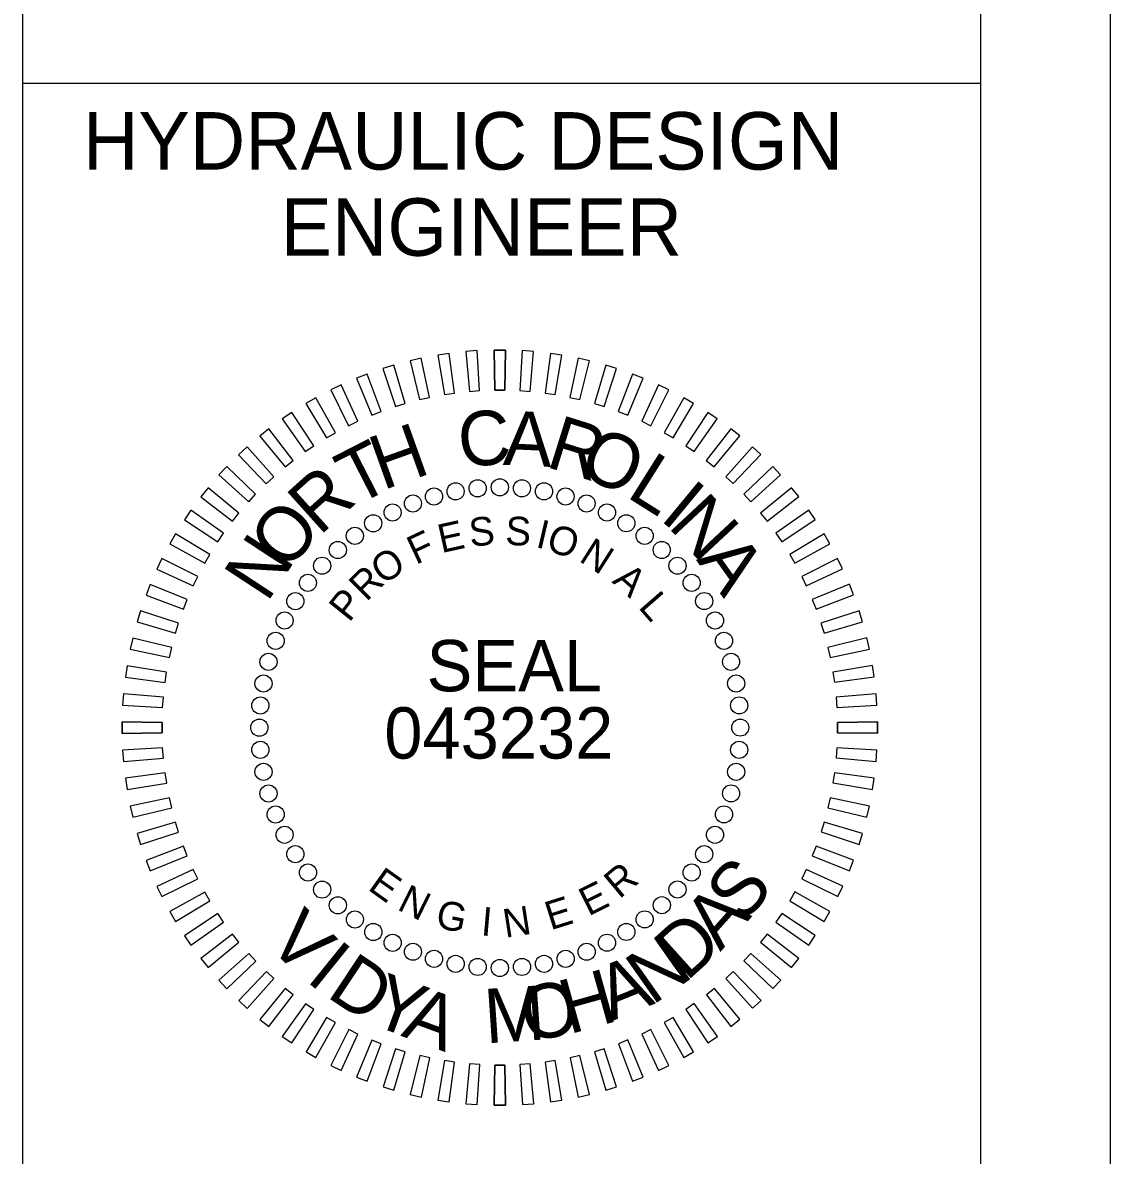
# Model space of a CAD drawing. Extents: x -0.56 to 3.44, y 0 to 1.83.
# Drawn here: x 2.6441 to 2.8333, y 1.3567 to 1.5538 of the extents above; entities that cross this region are included whole.
import ezdxf

# ---------------------------------------------------------------- set-up
doc = ezdxf.new("R2010")
doc.units = 0
for name, color, linetype in [('Default', 7, 'Continuous'), ('Scratch_Level_0', 7, 'Continuous'), ('Sheet PE Seal Cell', 7, 'Continuous'), ('Sheet Plan CELL', 7, 'Continuous'), ('Sheet_Plan_CELL', 7, 'Continuous')]:
    doc.layers.add(name, color=color, linetype=linetype)

msp = doc.modelspace()

# ---------------------------------------------------------------- linework, layer by layer
at = {"layer": 'Scratch_Level_0'}
msp.add_line((2.8333, 0), (2.8333, 1.8333), dxfattribs=at)
at = {"layer": 'Sheet PE Seal Cell'}
for p, q in [((2.71827, 1.49622), (2.7163, 1.49593)), ((2.7192, 1.48932), (2.71827, 1.49622)), ((2.72316, 1.4967), (2.72118, 1.49655)), ((2.72118, 1.49655), (2.7218, 1.48961)), ((2.72358, 1.48974), (2.72316, 1.4967)), ((2.72808, 1.49681), (2.72609, 1.49681)), ((2.72609, 1.49681), (2.7262, 1.48984)), ((2.72609, 1.49681), (2.72808, 1.49681)), ((2.7262, 1.48984), (2.72609, 1.49681)), ((2.72797, 1.48984), (2.72808, 1.49681)), ((2.72808, 1.49681), (2.72797, 1.48984)), ((2.731, 1.4967), (2.73059, 1.48974)), ((2.73298, 1.49655), (2.731, 1.4967)), ((2.73237, 1.48961), (2.73298, 1.49655)), ((2.73589, 1.49623), (2.73496, 1.48932)), ((2.73786, 1.49593), (2.73589, 1.49623)), ((2.70866, 1.49419), (2.70677, 1.49359)), ((2.71062, 1.4875), (2.70866, 1.49419)), ((2.71343, 1.49539), (2.71148, 1.49495)), ((2.71148, 1.49495), (2.71314, 1.48817)), ((2.71487, 1.48857), (2.71343, 1.49539)), ((2.7163, 1.49593), (2.71745, 1.48905)), ((2.73672, 1.48905), (2.73786, 1.49593)), ((2.74073, 1.49539), (2.73928, 1.48857)), ((2.74268, 1.49495), (2.74073, 1.49539)), ((2.74103, 1.48817), (2.74268, 1.49495)), ((2.74551, 1.49419), (2.74355, 1.48749)), ((2.7474, 1.4936), (2.74551, 1.49419)), ((2.70399, 1.49263), (2.70214, 1.4919)), ((2.70645, 1.4861), (2.70399, 1.49263)), ((2.70677, 1.49359), (2.70892, 1.48697)), ((2.74525, 1.48697), (2.7474, 1.4936)), ((2.75016, 1.49263), (2.74771, 1.48611)), ((2.75202, 1.49191), (2.75016, 1.49263)), ((2.69947, 1.49073), (2.69767, 1.48987)), ((2.70239, 1.48441), (2.69947, 1.49073)), ((2.70214, 1.4919), (2.7048, 1.48545)), ((2.74937, 1.48546), (2.75202, 1.49191)), ((2.7547, 1.49074), (2.75177, 1.48442)), ((2.75649, 1.48987), (2.7547, 1.49074)), ((2.69509, 1.4885), (2.69337, 1.48751)), ((2.69849, 1.48241), (2.69509, 1.4885)), ((2.69767, 1.48987), (2.70079, 1.48363)), ((2.71314, 1.48817), (2.71487, 1.48857)), ((2.71745, 1.48905), (2.7192, 1.48932)), ((2.7218, 1.48961), (2.72358, 1.48974)), ((2.7262, 1.48984), (2.72797, 1.48984)), ((2.72797, 1.48984), (2.7262, 1.48984)), ((2.73059, 1.48974), (2.73237, 1.48961)), ((2.73496, 1.48932), (2.73672, 1.48905)), ((2.73928, 1.48857), (2.74103, 1.48817)), ((2.75338, 1.48364), (2.75649, 1.48987)), ((2.75908, 1.48851), (2.75568, 1.48242)), ((2.7608, 1.48751), (2.75908, 1.48851)), ((2.69337, 1.48751), (2.69694, 1.48152)), ((2.70892, 1.48697), (2.71062, 1.4875)), ((2.74355, 1.48749), (2.74525, 1.48697)), ((2.75723, 1.48153), (2.7608, 1.48751)), ((2.69089, 1.48595), (2.68924, 1.48483)), ((2.68924, 1.48483), (2.69326, 1.47913)), ((2.69473, 1.48014), (2.69089, 1.48595)), ((2.70079, 1.48363), (2.70239, 1.48441)), ((2.7048, 1.48545), (2.70645, 1.4861)), ((2.74771, 1.48611), (2.74937, 1.48546)), ((2.75177, 1.48442), (2.75338, 1.48364)), ((2.76328, 1.48596), (2.75944, 1.48014)), ((2.76091, 1.47914), (2.76493, 1.48484)), ((2.76493, 1.48484), (2.76328, 1.48596)), ((2.68689, 1.48309), (2.68533, 1.48184)), ((2.69115, 1.47758), (2.68689, 1.48309)), ((2.69694, 1.48152), (2.69849, 1.48241)), ((2.75568, 1.48242), (2.75723, 1.48153)), ((2.76727, 1.4831), (2.76301, 1.47759)), ((2.76883, 1.48185), (2.76727, 1.4831)), ((2.68533, 1.48184), (2.68976, 1.47647)), ((2.76441, 1.47647), (2.76883, 1.48185)), ((2.68312, 1.47994), (2.68165, 1.47859)), ((2.68165, 1.47859), (2.68647, 1.47355)), ((2.68778, 1.47476), (2.68312, 1.47994)), ((2.69326, 1.47913), (2.69473, 1.48014)), ((2.75944, 1.48014), (2.76091, 1.47914)), ((2.77105, 1.47995), (2.76639, 1.47476)), ((2.7677, 1.47356), (2.77251, 1.4786)), ((2.77251, 1.4786), (2.77105, 1.47995)), ((2.67959, 1.47652), (2.67823, 1.47506)), ((2.68462, 1.4717), (2.67959, 1.47652)), ((2.68976, 1.47647), (2.69115, 1.47758)), ((2.76301, 1.47759), (2.76441, 1.47647)), ((2.77458, 1.47653), (2.76955, 1.47171)), ((2.77594, 1.47507), (2.77458, 1.47653)), ((2.67823, 1.47506), (2.68342, 1.47039)), ((2.68647, 1.47355), (2.68778, 1.47476)), ((2.76639, 1.47476), (2.7677, 1.47356)), ((2.77075, 1.4704), (2.77594, 1.47507)), ((2.67633, 1.47284), (2.67508, 1.47128)), ((2.68171, 1.46841), (2.67633, 1.47284)), ((2.77784, 1.47285), (2.77246, 1.46842)), ((2.77909, 1.47129), (2.77784, 1.47285)), ((2.67508, 1.47128), (2.68059, 1.46701)), ((2.68342, 1.47039), (2.68462, 1.4717)), ((2.76955, 1.47171), (2.77075, 1.4704)), ((2.77358, 1.46704), (2.77909, 1.47129)), ((2.67334, 1.46893), (2.67223, 1.46728)), ((2.67905, 1.46491), (2.67334, 1.46893)), ((2.78083, 1.46894), (2.77512, 1.46493)), ((2.78194, 1.4673), (2.78083, 1.46894)), ((2.67223, 1.46728), (2.67804, 1.46344)), ((2.68059, 1.46701), (2.68171, 1.46841)), ((2.77246, 1.46842), (2.77358, 1.46704)), ((2.77613, 1.46345), (2.78194, 1.4673)), ((2.67067, 1.46481), (2.66967, 1.46308)), ((2.67666, 1.46123), (2.67067, 1.46481)), ((2.67804, 1.46344), (2.67905, 1.46491)), ((2.77512, 1.46493), (2.77613, 1.46345)), ((2.7835, 1.46482), (2.77752, 1.46125)), ((2.7845, 1.4631), (2.7835, 1.46482)), ((2.66967, 1.46308), (2.67577, 1.45969)), ((2.7784, 1.4597), (2.7845, 1.4631)), ((2.67577, 1.45969), (2.67666, 1.46123)), ((2.77752, 1.46125), (2.7784, 1.4597)), ((2.66831, 1.4605), (2.66744, 1.4587)), ((2.66744, 1.4587), (2.67377, 1.45578)), ((2.67455, 1.45738), (2.66831, 1.4605)), ((2.78586, 1.46051), (2.77963, 1.45739)), ((2.78041, 1.45579), (2.78673, 1.45871)), ((2.78673, 1.45871), (2.78586, 1.46051)), ((2.67377, 1.45578), (2.67455, 1.45738)), ((2.77963, 1.45739), (2.78041, 1.45579)), ((2.66628, 1.45603), (2.66555, 1.45416)), ((2.67273, 1.45338), (2.66628, 1.45603)), ((2.7879, 1.45604), (2.78145, 1.45339)), ((2.78862, 1.45419), (2.7879, 1.45604)), ((2.66555, 1.45416), (2.67208, 1.45172)), ((2.67208, 1.45172), (2.67273, 1.45338)), ((2.78145, 1.45339), (2.7821, 1.45173)), ((2.7821, 1.45173), (2.78862, 1.45419)), ((2.66459, 1.4514), (2.66399, 1.44951)), ((2.67121, 1.44925), (2.66459, 1.4514)), ((2.78959, 1.45142), (2.78296, 1.44926)), ((2.79018, 1.44952), (2.78959, 1.45142)), ((2.66399, 1.44951), (2.67069, 1.44755)), ((2.67069, 1.44755), (2.67121, 1.44925)), ((2.78296, 1.44926), (2.78349, 1.44756)), ((2.78349, 1.44756), (2.79018, 1.44952)), ((2.66323, 1.44668), (2.66279, 1.44474)), ((2.67001, 1.44503), (2.66323, 1.44668)), ((2.66961, 1.44329), (2.67001, 1.44503)), ((2.79094, 1.4467), (2.78417, 1.44504)), ((2.78417, 1.44504), (2.78457, 1.44331)), ((2.79139, 1.44475), (2.79094, 1.4467)), ((2.66279, 1.44474), (2.66961, 1.44329)), ((2.78457, 1.44331), (2.79139, 1.44475)), ((2.66225, 1.44187), (2.66196, 1.4399)), ((2.66913, 1.44072), (2.66225, 1.44187)), ((2.79193, 1.44188), (2.78504, 1.44073)), ((2.79222, 1.43991), (2.79193, 1.44188)), ((2.66196, 1.4399), (2.66886, 1.43897)), ((2.66886, 1.43897), (2.66913, 1.44072)), ((2.78504, 1.44073), (2.78531, 1.43898)), ((2.78531, 1.43898), (2.79222, 1.43991)), ((2.66163, 1.43699), (2.66148, 1.435)), ((2.66857, 1.43637), (2.66163, 1.43699)), ((2.79254, 1.437), (2.78561, 1.43638)), ((2.7927, 1.43502), (2.79254, 1.437)), ((2.66148, 1.435), (2.66844, 1.43459)), ((2.66844, 1.43459), (2.66857, 1.43637)), ((2.78561, 1.43638), (2.78574, 1.43461)), ((2.78574, 1.43461), (2.7927, 1.43502)), ((2.66137, 1.43208), (2.66137, 1.43009)), ((2.66835, 1.43197), (2.66137, 1.43208)), ((2.66137, 1.43009), (2.66137, 1.43208)), ((2.66137, 1.43208), (2.66835, 1.43197)), ((2.66835, 1.4302), (2.66835, 1.43197)), ((2.66835, 1.43197), (2.66835, 1.4302)), ((2.7928, 1.4321), (2.78583, 1.43199)), ((2.78583, 1.43199), (2.7928, 1.4321)), ((2.78583, 1.43199), (2.78583, 1.43021)), ((2.78583, 1.43021), (2.78583, 1.43199)), ((2.7928, 1.43011), (2.7928, 1.4321)), ((2.7928, 1.4321), (2.7928, 1.43011)), ((2.66137, 1.43009), (2.66835, 1.4302)), ((2.66835, 1.4302), (2.66137, 1.43009)), ((2.78583, 1.43021), (2.7928, 1.43011)), ((2.7928, 1.43011), (2.78583, 1.43021)), ((2.66844, 1.42758), (2.66148, 1.42717)), ((2.66148, 1.42717), (2.66164, 1.42519)), ((2.66857, 1.4258), (2.66844, 1.42758)), ((2.78574, 1.42759), (2.78561, 1.42582)), ((2.7927, 1.42718), (2.78574, 1.42759)), ((2.79255, 1.4252), (2.7927, 1.42718)), ((2.66164, 1.42519), (2.66857, 1.4258)), ((2.78561, 1.42582), (2.79255, 1.4252)), ((2.66887, 1.42321), (2.66196, 1.42228)), ((2.66914, 1.42145), (2.66887, 1.42321)), ((2.78532, 1.42322), (2.78504, 1.42147)), ((2.79222, 1.42229), (2.78532, 1.42322)), ((2.66196, 1.42228), (2.66225, 1.42031)), ((2.66225, 1.42031), (2.66914, 1.42145)), ((2.78504, 1.42147), (2.79193, 1.42032)), ((2.79193, 1.42032), (2.79222, 1.42229)), ((2.66961, 1.41888), (2.66279, 1.41744)), ((2.66279, 1.41744), (2.66324, 1.41549)), ((2.67001, 1.41715), (2.66961, 1.41888)), ((2.78457, 1.4189), (2.78417, 1.41716)), ((2.79139, 1.41745), (2.78457, 1.4189)), ((2.79094, 1.4155), (2.79139, 1.41745)), ((2.66324, 1.41549), (2.67001, 1.41715)), ((2.78417, 1.41716), (2.79094, 1.4155)), ((2.67069, 1.41462), (2.664, 1.41266)), ((2.67122, 1.41292), (2.67069, 1.41462)), ((2.78349, 1.41464), (2.78297, 1.41294)), ((2.79019, 1.41268), (2.78349, 1.41464)), ((2.664, 1.41266), (2.66459, 1.41077)), ((2.66459, 1.41077), (2.67122, 1.41292)), ((2.78297, 1.41294), (2.78959, 1.41078)), ((2.78959, 1.41078), (2.79019, 1.41268)), ((2.67208, 1.41046), (2.66556, 1.408)), ((2.67273, 1.4088), (2.67208, 1.41046)), ((2.7821, 1.41047), (2.78145, 1.40881)), ((2.78863, 1.40802), (2.7821, 1.41047)), ((2.66556, 1.408), (2.66628, 1.40615)), ((2.66628, 1.40615), (2.67273, 1.4088)), ((2.78145, 1.40881), (2.7879, 1.40616)), ((2.7879, 1.40616), (2.78863, 1.40802)), ((2.67377, 1.4064), (2.66745, 1.40347)), ((2.67455, 1.4048), (2.67377, 1.4064)), ((2.78041, 1.40641), (2.77963, 1.40481)), ((2.78674, 1.40349), (2.78041, 1.40641)), ((2.66745, 1.40347), (2.66832, 1.40168)), ((2.66832, 1.40168), (2.67455, 1.4048)), ((2.77963, 1.40481), (2.78587, 1.40169)), ((2.78587, 1.40169), (2.78674, 1.40349)), ((2.67577, 1.40249), (2.66968, 1.39909)), ((2.67666, 1.40094), (2.67577, 1.40249)), ((2.77841, 1.4025), (2.77752, 1.40095)), ((2.78451, 1.3991), (2.77841, 1.4025)), ((2.67068, 1.39737), (2.67666, 1.40094)), ((2.77752, 1.40095), (2.78351, 1.39738)), ((2.66968, 1.39909), (2.67068, 1.39737)), ((2.67805, 1.39873), (2.67224, 1.39489)), ((2.67905, 1.39726), (2.67805, 1.39873)), ((2.77614, 1.39875), (2.77513, 1.39727)), ((2.78195, 1.3949), (2.77614, 1.39875)), ((2.78351, 1.39738), (2.78451, 1.3991)), ((2.67335, 1.39325), (2.67905, 1.39726)), ((2.77513, 1.39727), (2.78084, 1.39326)), ((2.67224, 1.39489), (2.67335, 1.39325)), ((2.6806, 1.39515), (2.67509, 1.3909)), ((2.67634, 1.38934), (2.68172, 1.39377)), ((2.68172, 1.39377), (2.6806, 1.39515)), ((2.77358, 1.39517), (2.77247, 1.39378)), ((2.77247, 1.39378), (2.77785, 1.38935)), ((2.77909, 1.39091), (2.77358, 1.39517)), ((2.78084, 1.39326), (2.78195, 1.3949)), ((2.68343, 1.39179), (2.67824, 1.38712)), ((2.68463, 1.39048), (2.68343, 1.39179)), ((2.77076, 1.3918), (2.76956, 1.39049)), ((2.77595, 1.38713), (2.77076, 1.3918)), ((2.67509, 1.3909), (2.67634, 1.38934)), ((2.6796, 1.38566), (2.68463, 1.39048)), ((2.76956, 1.39049), (2.77459, 1.38567)), ((2.77785, 1.38935), (2.77909, 1.39091)), ((2.68648, 1.38863), (2.68167, 1.38359)), ((2.68779, 1.38742), (2.68648, 1.38863)), ((2.76771, 1.38863), (2.7664, 1.38743)), ((2.77253, 1.3836), (2.76771, 1.38863)), ((2.67824, 1.38712), (2.6796, 1.38566)), ((2.68313, 1.38224), (2.68779, 1.38742)), ((2.7664, 1.38743), (2.77106, 1.38225)), ((2.77459, 1.38567), (2.77595, 1.38713)), ((2.68977, 1.38571), (2.68535, 1.38033)), ((2.6869, 1.37909), (2.69117, 1.3846)), ((2.69117, 1.3846), (2.68977, 1.38571)), ((2.76442, 1.38572), (2.76303, 1.38461)), ((2.76303, 1.38461), (2.76729, 1.3791)), ((2.76885, 1.38034), (2.76442, 1.38572)), ((2.68167, 1.38359), (2.68313, 1.38224)), ((2.69327, 1.38305), (2.68925, 1.37735)), ((2.6909, 1.37623), (2.69474, 1.38204)), ((2.69474, 1.38204), (2.69327, 1.38305)), ((2.76092, 1.38306), (2.75945, 1.38205)), ((2.75945, 1.38205), (2.76329, 1.37624)), ((2.76494, 1.37735), (2.76092, 1.38306)), ((2.77106, 1.38225), (2.77253, 1.3836)), ((2.68535, 1.38033), (2.6869, 1.37909)), ((2.69695, 1.38066), (2.69338, 1.37467)), ((2.6985, 1.37977), (2.69695, 1.38066)), ((2.75724, 1.38067), (2.75569, 1.37978)), ((2.76081, 1.37468), (2.75724, 1.38067)), ((2.76729, 1.3791), (2.76885, 1.38034)), ((2.6951, 1.37368), (2.6985, 1.37977)), ((2.7008, 1.37855), (2.69769, 1.37231)), ((2.70241, 1.37777), (2.7008, 1.37855)), ((2.75339, 1.37856), (2.75179, 1.37778)), ((2.75651, 1.37232), (2.75339, 1.37856)), ((2.75569, 1.37978), (2.75909, 1.37368)), ((2.68925, 1.37735), (2.6909, 1.37623)), ((2.69948, 1.37145), (2.70241, 1.37777)), ((2.70481, 1.37673), (2.70216, 1.37028)), ((2.70402, 1.36955), (2.70646, 1.37608)), ((2.70646, 1.37608), (2.70481, 1.37673)), ((2.74938, 1.37674), (2.74773, 1.37609)), ((2.74773, 1.37609), (2.75019, 1.36956)), ((2.75204, 1.37029), (2.74938, 1.37674)), ((2.75179, 1.37778), (2.75471, 1.37145)), ((2.76329, 1.37624), (2.76494, 1.37735)), ((2.69338, 1.37467), (2.6951, 1.37368)), ((2.70893, 1.37522), (2.70678, 1.36859)), ((2.70867, 1.368), (2.71063, 1.3747)), ((2.71063, 1.3747), (2.70893, 1.37522)), ((2.71315, 1.37402), (2.7115, 1.36724)), ((2.7149, 1.37361), (2.71315, 1.37402)), ((2.74104, 1.37402), (2.73931, 1.37362)), ((2.74269, 1.36724), (2.74104, 1.37402)), ((2.74526, 1.37522), (2.74356, 1.37469)), ((2.74356, 1.37469), (2.74552, 1.368)), ((2.74741, 1.3686), (2.74526, 1.37522)), ((2.75909, 1.37368), (2.76081, 1.37468)), ((2.69769, 1.37231), (2.69948, 1.37145)), ((2.71345, 1.3668), (2.7149, 1.37361)), ((2.71746, 1.37314), (2.71632, 1.36625)), ((2.71922, 1.37287), (2.71746, 1.37314)), ((2.71829, 1.36596), (2.71922, 1.37287)), ((2.72181, 1.37258), (2.7212, 1.36564)), ((2.72359, 1.37245), (2.72181, 1.37258)), ((2.72318, 1.36549), (2.72359, 1.37245)), ((2.72621, 1.37235), (2.7261, 1.36538)), ((2.7261, 1.36538), (2.72621, 1.37235)), ((2.72798, 1.37235), (2.72621, 1.37235)), ((2.72621, 1.37235), (2.72798, 1.37235)), ((2.72809, 1.36538), (2.72798, 1.37235)), ((2.72798, 1.37235), (2.72809, 1.36538)), ((2.73238, 1.37258), (2.7306, 1.37245)), ((2.7306, 1.37245), (2.73102, 1.36549)), ((2.733, 1.36564), (2.73238, 1.37258)), ((2.73673, 1.37314), (2.73498, 1.37287)), ((2.73498, 1.37287), (2.73591, 1.36596)), ((2.73788, 1.36626), (2.73673, 1.37314)), ((2.73931, 1.37362), (2.74075, 1.3668)), ((2.75471, 1.37145), (2.75651, 1.37232)), ((2.70216, 1.37028), (2.70402, 1.36955)), ((2.75019, 1.36956), (2.75204, 1.37029)), ((2.70678, 1.36859), (2.70867, 1.368)), ((2.74552, 1.368), (2.74741, 1.3686)), ((2.7115, 1.36724), (2.71345, 1.3668)), ((2.71632, 1.36625), (2.71829, 1.36596)), ((2.73591, 1.36596), (2.73788, 1.36626)), ((2.74075, 1.3668), (2.74269, 1.36724)), ((2.7212, 1.36564), (2.72318, 1.36549)), ((2.7261, 1.36538), (2.72809, 1.36538)), ((2.72809, 1.36538), (2.7261, 1.36538)), ((2.73102, 1.36549), (2.733, 1.36564))]:
    msp.add_line(p, q, dxfattribs=at)
for centre in [(2.71564, 1.47132), (2.7194, 1.47221), (2.72323, 1.47274), (2.72709, 1.47292), (2.73094, 1.47274), (2.73477, 1.47221), (2.73853, 1.47132), (2.71198, 1.47009), (2.74219, 1.4701), (2.70844, 1.46853), (2.74573, 1.46854), (2.70507, 1.46665), (2.7491, 1.46666), (2.70188, 1.46447), (2.75229, 1.46447), (2.69891, 1.462), (2.75526, 1.46201), (2.69618, 1.45927), (2.758, 1.45927), (2.69371, 1.4563), (2.76046, 1.4563), (2.69153, 1.45311), (2.76265, 1.45312), (2.68965, 1.44973), (2.76453, 1.44974), (2.68809, 1.4462), (2.76609, 1.44621), (2.68686, 1.44254), (2.76732, 1.44254), (2.68598, 1.43877), (2.7682, 1.43878), (2.68544, 1.43495), (2.76874, 1.43496), (2.68526, 1.43109), (2.76892, 1.4311), (2.68544, 1.42723), (2.76874, 1.42724), (2.68598, 1.4234), (2.7682, 1.42341), (2.68686, 1.41964), (2.76732, 1.41965), (2.68809, 1.41598), (2.76609, 1.41599), (2.68965, 1.41245), (2.76453, 1.41245), (2.69153, 1.40907), (2.76265, 1.40908), (2.69372, 1.40588), (2.76047, 1.40589), (2.69618, 1.40291), (2.758, 1.40292), (2.69892, 1.40018), (2.75527, 1.40019), (2.70189, 1.39771), (2.7523, 1.39772), (2.70508, 1.39553), (2.74911, 1.39554), (2.70845, 1.39365), (2.74574, 1.39366), (2.71198, 1.39209), (2.71565, 1.39086), (2.73854, 1.39087), (2.7422, 1.39209), (2.71941, 1.38998), (2.72324, 1.38945), (2.72709, 1.38927), (2.73095, 1.38945), (2.73478, 1.38998)]:
    msp.add_circle(centre, 0.00149, dxfattribs=at)
at = {"layer": 'Sheet Plan CELL'}
msp.add_line((2.81079, 1.54318), (2.64412, 1.54318), dxfattribs=at)
at = {"layer": 'Sheet_Plan_CELL'}
for p, q in [((2.64409, 0.0375), (2.64413, 1.7958)), ((2.81075, 0.0375), (2.81079, 1.7958))]:
    msp.add_line(p, q, dxfattribs=at)

# ---------------------------------------------------------------- texts
at = {"layer": 'Default'}
for s, height, p in [('HYDRAULIC DESIGN', 0.0100002, (2.65457, 1.52821)), ('ENGINEER', 0.01, (2.68896, 1.51321))]:
    msp.add_text(s, height=height, dxfattribs=at).set_placement(p)
at = {"layer": 'Sheet PE Seal Cell'}
for s, height, rotation, p in [('C', 0.00946, 4.8764, (2.72021, 1.47638)), ('A', 0.00946, 357.4697, (2.72758, 1.47683)), ('R', 0.00946, 342.6561, (2.73486, 1.47656)), ('H', 0.00946, 19.69, (2.70671, 1.47235)), ('O', 0.00946, 335.2494, (2.74036, 1.47531)), ('T', 0.00946, 27.0968, (2.70195, 1.46957)), ('L', 0.00946, 327.8426, (2.74889, 1.47138)), ('R', 0.00946, 41.9103, (2.69571, 1.46435)), ('I', 0.00946, 320.4358, (2.75473, 1.46739)), ('N', 0.00946, 313.029, (2.75617, 1.46612)), ('O', 0.00946, 49.3171, (2.69001, 1.45807)), ('E', 0.00498, 12.4424, (2.71693, 1.46145)), ('S', 0.00498, 5.8595, (2.72198, 1.46256)), ('S', 0.00498, 357.6261, (2.72799, 1.46291)), ('I', 0.00498, 346.864, (2.73317, 1.46252)), ('N', 0.00946, 56.7238, (2.68659, 1.4527)), ('F', 0.00498, 25.1312, (2.71249, 1.45939)), ('O', 0.00498, 341.1523, (2.73492, 1.46205)), ('N', 0.00498, 327.4409, (2.74068, 1.46017)), ('A', 0.00946, 305.6223, (2.76119, 1.46031)), ('O', 0.00498, 31.9602, (2.70668, 1.45587)), ('R', 0.00498, 44.8845, (2.70388, 1.45288)), ('A', 0.00498, 318.4839, (2.74647, 1.45644)), ('P', 0.00498, 51.2911, (2.70088, 1.44927)), ('L', 0.00498, 310.9631, (2.75105, 1.45203)), ('SEAL', 0.008929, 0.0065, (2.71435, 1.43742)), ('043232', 0.008929, 0.0065, (2.707, 1.42571)), ('S', 0.00946, 48.2783, (2.76932, 1.39679)), ('E', 0.00498, 324.5809, (2.70395, 1.403)), ('R', 0.00498, 39.8291, (2.74789, 1.40117)), ('N', 0.00498, 333.5524, (2.70906, 1.39952)), ('E', 0.00498, 26.3005, (2.7425, 1.39821)), ('E', 0.00498, 17.5603, (2.73592, 1.3958)), ('A', 0.00946, 48.2783, (2.76545, 1.39203)), ('V', 0.00946, 315.2122, (2.68639, 1.39347)), ('G', 0.00498, 348.7213, (2.71573, 1.39634)), ('I', 0.00498, 355.1208, (2.72372, 1.39496)), ('N', 0.00498, 8.8227, (2.72804, 1.3945)), ('D', 0.00946, 41.983, (2.75954, 1.3868)), ('I', 0.00946, 321.0677, (2.69318, 1.38713)), ('N', 0.00946, 35.0638, (2.75358, 1.38264)), ('D', 0.00946, 326.4569, (2.69672, 1.3844)), ('A', 0.00946, 22.1313, (2.74648, 1.37996)), ('Y', 0.00946, 339.9293, (2.70413, 1.37966)), ('H', 0.00946, 15.6022, (2.73912, 1.37769)), ('M', 0.00946, 3.834, (2.72467, 1.37614)), ('O', 0.00946, 9.9111, (2.73167, 1.37639)), ('A', 0.00946, 339.9293, (2.70974, 1.3775))]:
    msp.add_text(s, height=height, rotation=rotation, dxfattribs=at).set_placement(p)

doc.saveas('drawing.dxf')
